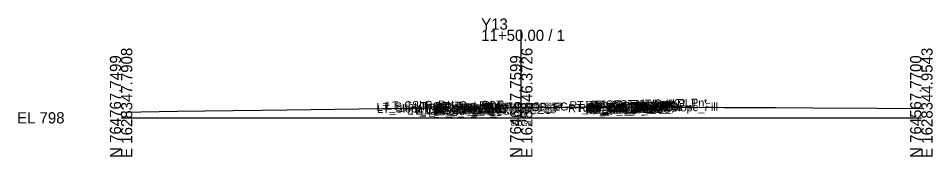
# Model space of a CAD drawing. Extents: x -26 to 203, y -10 to 3517.
# Drawn here: x -25.7 to 202.8, y 2990.3 to 3024.8 of the extents above; entities that cross this region are included whole.
import ezdxf

# ---------------------------------------------------------------- set-up
doc = ezdxf.new("R2010")
doc.units = 0
for name, color, linetype in [('Default', 7, 'Continuous'), ('Exist CMT Pavement', 7, 'Continuous'), ('Exist Cross Section Cell', 7, 'Continuous'), ('Exist XS Center Line Elevation Label', 7, 'Continuous'), ('Exist XS Ground Line', 7, 'Continuous'), ('Scratch_Level_0', 7, 'Continuous')]:
    doc.layers.add(name, color=color, linetype=linetype)

msp = doc.modelspace()

# ---------------------------------------------------------------- linework, layer by layer
at = {"layer": 'Exist CMT Pavement'}
msp.add_lwpolyline([(100, 3002.59), (111.76, 3002.69), (113.84, 3002.68), (115.01, 3002.69), (117.8, 3002.67), (126.84, 3002.66)], dxfattribs=at)
at = {"layer": 'Exist Cross Section Cell'}
for p, q in [((100, 3000), (100, 3021.98)), ((0, 3000), (100, 3000)), ((100, 3000), (200, 3000))]:
    msp.add_line(p, q, dxfattribs=at)
at = {"layer": 'Exist XS Ground Line'}
msp.add_lwpolyline([(0, 3001.42), (0.38, 3001.43), (14.11, 3001.69), (20.91, 3001.77), (35.1, 3001.95), (41.45, 3002.02), (65.32, 3002.31), (66.8, 3002.32), (75.92, 3002.4), (94.13, 3002.53), (94.75, 3002.53), (95.81, 3002.56), (100, 3002.59), (111.76, 3002.69), (113.84, 3002.68), (115.01, 3002.69), (117.8, 3002.67), (140.69, 3002.64), (150.62, 3002.57), (163.52, 3002.54), (172.89, 3002.48), (188.86, 3002.4), (200, 3002.31)], dxfattribs=at)

# ---------------------------------------------------------------- texts
at = {"layer": 'Default'}
msp.add_text('-', height=0.0001, dxfattribs=at).set_placement((0, 3000))
at = {"layer": 'Exist Cross Section Cell'}
for s, p in [('Y13', (90, 3021.98)), ('11+50.00 / 1', (90, 3019.18)), ('EL 798', (-26, 2998.6))]:
    msp.add_text(s, height=2.8, dxfattribs=at).set_placement(p)
for s, p in [('E 1628347.7908', (2.8, 2990)), ('E 1628346.3726', (102.8, 2990)), ('E 1628344.9543', (202.8, 2990)), ('N 764767.7499', (0, 2990)), ('N 764667.7599', (100, 2990)), ('N 764567.7700', (200, 2990))]:
    msp.add_text(s, height=2.8, rotation=90, dxfattribs=at).set_placement(p)
at = {"layer": 'Exist XS Center Line Elevation Label'}
msp.add_text('800.59', height=1.2, dxfattribs=at).set_placement((97.41, 2997.99))
at = {"layer": 'Scratch_Level_0'}
for s, p in [('LT_Sub_Trench_Out_DLT', (63.86, 3001.7)), ('LT_Slope_Fill', (63.98, 3001.19)), ('LT_CSLP_Pnt', (66.19, 3002.03)), ('LT_CG1_Shelf_Out', (71.57, 3000.76)), ('LT_CG_Top_Face', (73.28, 3001.79)), ('LT_CG_Top_BOC', (73.8, 3001.81)), ('LT_CG_Bot_BOC', (73.84, 3000.8)), ('LT_CG_Top_Gut', (74.26, 3001.31)), ('LT_CG_Bot_IE', (77.94, 3000.86)), ('LT_PV2_OEOT', (78.2, 3001.19)), ('LT_PV3_OEOT', (78.2, 3000.86)), ('LT_PV1_OEOT', (78.76, 3001.46)), ('RT_PV_IEEOP_EG', (88.16, 3001.36)), ('LT_Sub_OEEOP', (89.23, 3000.63)), ('LT_PV2_OEEOP', (89.33, 3001.3)), ('LT_PV3_OEEOP', (89.33, 3000.96)), ('LT_PV1_OEEOP', (89.9, 3001.43)), ('RT_PV2_IEEOP', (89.93, 3001.31)), ('RT_PV3_IEEOP', (89.93, 3000.98)), ('LT_PV2_IEEOP', (89.97, 3001.31)), ('RT_PV1_IEEOP', (90.49, 3001.44)), ('LT_PV1_IEEOP', (90.54, 3001.45)), ('PV2_PGL', (93.93, 3001.39)), ('PV1_PGL', (94.49, 3001.65)), ('RT_PV_Sub_Tie_Out', (111.75, 3001.36)), ('RT_Sub_Trench_Out_DLT', (112.08, 3002.12)), ('RT_PV_OEEOP_EG', (114.36, 3001.41)), ('RT_Sub_OEEOP', (116.03, 3000.9)), ('RT_CG_Top_Face', (116.08, 3002.21)), ('RT_PV2_OEEOP', (116.12, 3001.56)), ('RT_PV3_OEEOP', (116.12, 3001.23)), ('RT_CG1_Shelf_Out', (116.37, 3001.21)), ('RT_PV1_OEEOP', (116.69, 3001.7)), ('RT_CG_Bot_IE', (116.73, 3001.24)), ('RT_Sub_OEOT', (116.9, 3000.91)), ('RT_PV2_OEOT', (116.99, 3001.58)), ('RT_PV3_OEOT', (116.99, 3001.25)), ('RT_CG_Top_Gut', (117.05, 3001.73)), ('RT_PV1_OEOT', (117.56, 3001.84)), ('RT_CG_Top_BOC', (117.6, 3002.23)), ('RT_CG_Bot_BOC', (117.63, 3001.24)), ('RT_Sub_OEOP', (120.26, 3000.95)), ('RT_CSLP_Pnt', (128.99, 3002.46)), ('RT_Slope_Fill', (132.42, 3001.44)), ('LT_Sub_OEOP', (74.8, 3000.49)), ('LT_Sub_OEOT', (78.1, 3000.53))]:
    msp.add_text(s, height=2, rotation=1.1458, dxfattribs=at).set_placement(p)

doc.saveas('drawing.dxf')
